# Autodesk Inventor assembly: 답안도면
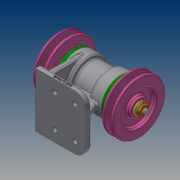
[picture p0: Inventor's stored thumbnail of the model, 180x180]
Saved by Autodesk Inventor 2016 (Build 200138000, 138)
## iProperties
Created: 2020-06
Part Number: 답안도면
Material: 일반
Document SubType Name: Assembly
Designer: 605-17
Author: 605-17
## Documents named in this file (12)
- C:\Users\605-17\Desktop\700606V1052\답안도면.iam
- C:\Users\605-17\Desktop\700606V1052\본체.ipt
- C:\Users\605-17\Desktop\700606V1052\베어링 6204.ipt
- C:\Users\605-17\Desktop\700606V1052\축.ipt
- C:\Users\605-17\Desktop\700606V1052\커버.ipt
- C:\Users\605-17\Desktop\700606V1052\볼트 M4.ipt
- C:\Users\605-17\Desktop\700606V1052\Ű 5x5x12.ipt
- C:\Users\605-17\Desktop\700606V1052\V-벨트풀리.ipt
- C:\Users\605-17\Desktop\700606V1052\평면 와셔 10x21.ipt
- C:\Users\605-17\Desktop\700606V1052\스프링 와셔 10.ipt
- C:\Users\605-17\Desktop\700606V1052\너트 M10.ipt
- C:\Users\605-17\Desktop\700606V1052\오일 실 20 32 5.ipt
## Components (4 placed, 2 different names)
1. Ű 5x5x12:1
2. Ű 5x5x12:2
3. V-벨트풀리:1
4. V-벨트풀리:2
